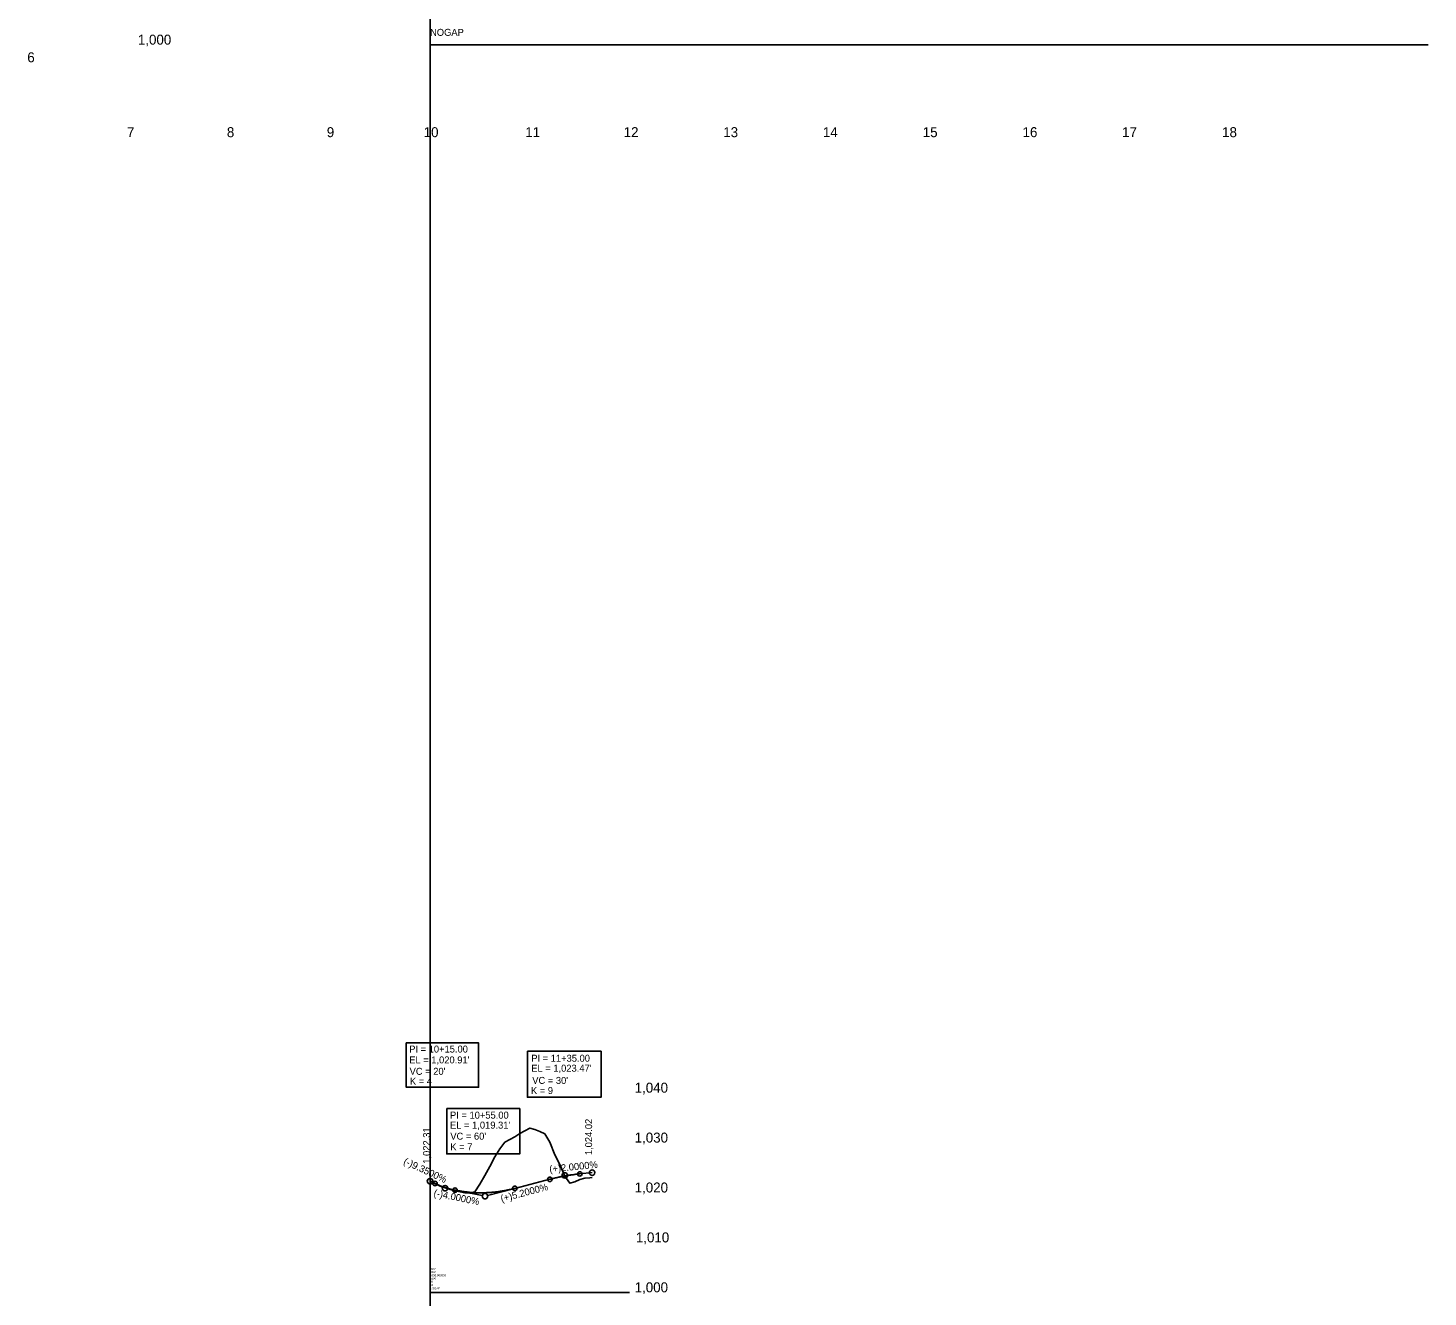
# Model space of a CAD drawing. Extents: x 1427711 to 1429114, y 853103 to 858103.
# Drawn here: x 1427711 to 1429114, y 855598 to 856869 of the extents above; entities that cross this region are included whole.
import ezdxf

# ---------------------------------------------------------------- set-up
doc = ezdxf.new("R2010")
doc.units = 0
for name, color, linetype in [('Exist Profile Cell', 7, 'Continuous'), ('Exist Vertical Profile Ground Line', 7, 'Continuous'), ('Exist Vertical Profile Horizontal Axis Label Major', 7, 'Continuous'), ('Exist Vertical Profile Vertical Axis Label', 7, 'Continuous'), ('Prop Grid Mask', 7, 'Continuous'), ('Prop Vertical Profile Curve Label', 7, 'Continuous'), ('Prop Vertical Profile Grade', 7, 'Continuous'), ('Prop Vertical Profile Grade Label', 7, 'Continuous'), ('Prop VPI Label', 7, 'Continuous')]:
    doc.layers.add(name, color=color, linetype=linetype)

msp = doc.modelspace()

# ---------------------------------------------------------------- linework, layer by layer
at = {"layer": 'Exist Profile Cell'}
for p, q in [((1428114, 856852.6), (1428114, 858102.6)), ((1428114, 856852.6), (1429114, 856852.6)), ((1428114, 856852.6), (1428114, 855602.6)), ((1428114, 855602.6), (1428114, 856852.6)), ((1428114, 855602.6), (1428314, 855602.6)), ((1428114, 855602.6), (1428114, 854352.6)), ((1428114, 854352.6), (1428114, 855602.6))]:
    msp.add_line(p, q, dxfattribs=at)
at = {"layer": 'Exist Vertical Profile Ground Line'}
msp.add_lwpolyline([(1428114, 855714.1), (1428119, 855711.4), (1428124, 855709.3), (1428129, 855707.4), (1428134, 855705.8), (1428139, 855704.5), (1428144, 855703.5), (1428149, 855702.6), (1428154, 855702), (1428159, 855703.5), (1428164, 855711.2), (1428169, 855719.9), (1428174, 855729), (1428179, 855738.6), (1428184, 855746.6), (1428189, 855753.2), (1428194, 855755.9), (1428199, 855758.6), (1428204, 855762), (1428209, 855764.7), (1428214, 855767.3), (1428219, 855766), (1428224, 855764), (1428229, 855761.4), (1428234, 855753.1), (1428239, 855740.4), (1428244, 855730.8), (1428249, 855719.1), (1428254, 855712.1), (1428259, 855713.6), (1428264, 855715.7), (1428269, 855717.2), (1428274, 855717.6), (1428276.3, 855717.8)], dxfattribs=at)
at = {"layer": 'Prop Grid Mask'}
for points in [[(1428090.2, 855852.6), (1428162.7, 855852.6), (1428162.7, 855808.3), (1428090.2, 855808.3)], [(1428211.6, 855844.3), (1428285.4, 855844.3), (1428285.4, 855798.3), (1428211.6, 855798.3)], [(1428130.8, 855786.9), (1428203.8, 855786.9), (1428203.8, 855741.5), (1428130.8, 855741.5)]]:
    msp.add_lwpolyline(points, close=True, dxfattribs=at)
at = {"layer": 'Prop Vertical Profile Curve Label'}
for centre in [(1428234, 855716), (1428264, 855721.4), (1428119, 855711.8), (1428139, 855705.1), (1428139, 855705.1), (1428199, 855706.9)]:
    msp.add_circle(centre, 2.25, dxfattribs=at)
at = {"layer": 'Prop Vertical Profile Grade'}
for p, q in [((1428199, 855706.9), (1428234, 855716)), ((1428264, 855721.4), (1428276.4, 855722.7)), ((1428114, 855714.1), (1428119, 855711.8))]:
    msp.add_line(p, q, dxfattribs=at)
for points in [[(1428234, 855716), (1428234.6, 855716.2), (1428235.2, 855716.3), (1428235.8, 855716.5), (1428236.4, 855716.6), (1428237, 855716.8), (1428237.6, 855716.9), (1428238.2, 855717.1), (1428238.8, 855717.2), (1428239.4, 855717.4), (1428240, 855717.5), (1428240.6, 855717.6), (1428241.2, 855717.8), (1428241.8, 855717.9), (1428242.4, 855718), (1428243, 855718.1), (1428243.6, 855718.3), (1428244.2, 855718.4), (1428244.8, 855718.5), (1428245.4, 855718.6), (1428246, 855718.8), (1428246.6, 855718.9), (1428247.2, 855719), (1428247.8, 855719.1), (1428248.4, 855719.2), (1428249, 855719.3), (1428249.6, 855719.4), (1428250.2, 855719.5), (1428250.8, 855719.6), (1428251.4, 855719.7), (1428252, 855719.8), (1428252.6, 855719.9), (1428253.2, 855720), (1428253.8, 855720.1), (1428254.4, 855720.2), (1428255, 855720.3), (1428255.6, 855720.4), (1428256.2, 855720.5), (1428256.8, 855720.6), (1428257.4, 855720.6), (1428258, 855720.7), (1428258.6, 855720.8), (1428259.2, 855720.9), (1428259.8, 855721), (1428260.4, 855721), (1428261, 855721.1), (1428261.6, 855721.2), (1428262.2, 855721.2), (1428262.8, 855721.3), (1428263.4, 855721.4), (1428264, 855721.4)], [(1428119, 855711.8), (1428119.4, 855711.6), (1428119.8, 855711.4), (1428120.2, 855711.2), (1428120.6, 855711.1), (1428121, 855710.9), (1428121.4, 855710.7), (1428121.8, 855710.5), (1428122.2, 855710.4), (1428122.6, 855710.2), (1428123, 855710), (1428123.4, 855709.9), (1428123.8, 855709.7), (1428124.2, 855709.5), (1428124.6, 855709.4), (1428125, 855709.2), (1428125.4, 855709.1), (1428125.8, 855708.9), (1428126.2, 855708.8), (1428126.6, 855708.6), (1428127, 855708.5), (1428127.4, 855708.3), (1428127.8, 855708.2), (1428128.2, 855708.1), (1428128.6, 855707.9), (1428129, 855707.8), (1428129.4, 855707.7), (1428129.8, 855707.5), (1428130.2, 855707.4), (1428130.6, 855707.3), (1428131, 855707.2), (1428131.4, 855707), (1428131.8, 855706.9), (1428132.2, 855706.8), (1428132.6, 855706.7), (1428133, 855706.6), (1428133.4, 855706.5), (1428133.8, 855706.3), (1428134.2, 855706.2), (1428134.6, 855706.1), (1428135, 855706), (1428135.4, 855705.9), (1428135.8, 855705.8), (1428136.2, 855705.7), (1428136.6, 855705.6), (1428137, 855705.6), (1428137.4, 855705.5), (1428137.8, 855705.4), (1428138.2, 855705.3), (1428138.6, 855705.2), (1428139, 855705.1)], [(1428139, 855705.1), (1428140.2, 855704.9), (1428141.4, 855704.7), (1428142.6, 855704.5), (1428143.8, 855704.3), (1428145, 855704.1), (1428146.2, 855703.9), (1428147.4, 855703.7), (1428148.6, 855703.6), (1428149.8, 855703.4), (1428151, 855703.3), (1428152.2, 855703.2), (1428153.4, 855703), (1428154.6, 855702.9), (1428155.8, 855702.8), (1428157, 855702.8), (1428158.2, 855702.7), (1428159.4, 855702.6), (1428160.6, 855702.6), (1428161.8, 855702.6), (1428163, 855702.5), (1428164.2, 855702.5), (1428165.4, 855702.5), (1428166.6, 855702.5), (1428167.8, 855702.5), (1428169, 855702.6), (1428170.2, 855702.6), (1428171.4, 855702.7), (1428172.6, 855702.7), (1428173.8, 855702.8), (1428175, 855702.9), (1428176.2, 855703), (1428177.4, 855703.1), (1428178.6, 855703.2), (1428179.8, 855703.3), (1428181, 855703.5), (1428182.2, 855703.6), (1428183.4, 855703.8), (1428184.6, 855704), (1428185.8, 855704.2), (1428187, 855704.4), (1428188.2, 855704.6), (1428189.4, 855704.8), (1428190.6, 855705), (1428191.8, 855705.3), (1428193, 855705.5), (1428194.2, 855705.8), (1428195.4, 855706), (1428196.6, 855706.3), (1428197.8, 855706.6), (1428199, 855706.9)]]:
    msp.add_spline(points, degree=3, dxfattribs=at)
at = {"layer": 'Prop VPI Label'}
for p, q in [((1428234, 855716), (1428246.3, 855719.2)), ((1428264, 855721.4), (1428251.7, 855720.2)), ((1428119, 855711.8), (1428126.5, 855708.3)), ((1428139, 855705.1), (1428131.7, 855706.6)), ((1428139, 855705.1), (1428166.3, 855699.7)), ((1428199, 855706.9), (1428171.7, 855699.8))]:
    msp.add_line(p, q, dxfattribs=at)
for centre in [(1428114, 855714.1), (1428249, 855719.9), (1428276.4, 855722.7), (1428129, 855707.1), (1428169, 855699.1)]:
    msp.add_circle(centre, 2.75, dxfattribs=at)

# ---------------------------------------------------------------- texts
at = {"layer": 'Exist Profile Cell'}
for s, height, p in [('NOGAP', 7, (1428114, 856861.6)), ('RDY', 2, (1428114, 855625.3)), ('DR2', 2, (1428114, 855622.1)), ('1000.000000', 2, (1428114, 855618.8)), ('1000', 2, (1428114, 855615.6)), ('50', 2, (1428114, 855612.3)), ('10', 2, (1428114, 855609.1)), ('NOGAP', 2, (1428114, 855605.8))]:
    msp.add_text(s, height=height, dxfattribs=at).set_placement(p)
at = {"layer": 'Exist Vertical Profile Horizontal Axis Label Major'}
for s, p in [('6', (1427710.4, 856835.1)), ('7', (1427810.3, 856760.1)), ('8', (1427910.4, 856760.1)), ('9', (1428010.5, 856760.1)), ('10', (1428107.6, 856760.1)), ('11', (1428209.4, 856760.1)), ('12', (1428308, 856760.1)), ('13', (1428407.8, 856760.1)), ('14', (1428507.6, 856760.1)), ('15', (1428607.7, 856760.1)), ('16', (1428707.7, 856760.1)), ('17', (1428807.5, 856760.1)), ('18', (1428907.7, 856760.1))]:
    msp.add_text(s, height=10, dxfattribs=at).set_placement(p)
at = {"layer": 'Exist Vertical Profile Vertical Axis Label'}
for s, p in [('1,000', (1427821.2, 856852.8)), ('1,040', (1428319, 855802.8)), ('1,030', (1428319, 855752.8)), ('1,020', (1428319, 855702.8)), ('1,010', (1428320.2, 855652.8)), ('1,000', (1428319, 855602.8))]:
    msp.add_text(s, height=10, dxfattribs=at).set_placement(p)
at = {"layer": 'Prop Vertical Profile Curve Label'}
for s, p in [("VC = 20'", (1428093.5, 855820.7)), ('K = 4', (1428093.8, 855810.8)), ("VC = 30'", (1428216.4, 855811.6)), ('K = 9', (1428215.1, 855801.4)), ("VC = 60'", (1428134.3, 855755.7)), ('K = 7', (1428134.3, 855745))]:
    msp.add_text(s, height=7, dxfattribs=at).set_placement(p)
at = {"layer": 'Prop Vertical Profile Grade Label'}
for s, rotation, p in [('(-)9.3500%', 334.9439, (1428086.7, 855731.7)), ('(+)2.0000%', 5.7106, (1428233.9, 855722.7)), ('(-)4.0000%', 348.6901, (1428117.2, 855699.1)), ('(+)5.2000%', 14.5742, (1428185.7, 855693.1))]:
    msp.add_text(s, height=7, rotation=rotation, dxfattribs=at).set_placement(p)
at = {"layer": 'Prop VPI Label'}
for s, p in [('PI = 10+15.00', (1428093.1, 855843)), ("EL = 1,020.91'", (1428093.1, 855832.1)), ('PI = 11+35.00', (1428215.4, 855833.8)), ("EL = 1,023.47'", (1428215.4, 855823.8)), ('PI = 10+55.00', (1428134, 855776.8)), ("EL = 1,019.31'", (1428134, 855766.8))]:
    msp.add_text(s, height=7, dxfattribs=at).set_placement(p)
for s, p in [('1,024.02', (1428276.4, 855740.2)), ('1,022.31', (1428114, 855731.6))]:
    msp.add_text(s, height=7, rotation=90, dxfattribs=at).set_placement(p)

doc.saveas('drawing.dxf')
